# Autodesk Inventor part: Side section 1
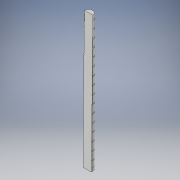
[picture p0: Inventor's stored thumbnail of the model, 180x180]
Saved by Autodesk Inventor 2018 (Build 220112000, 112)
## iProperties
Created: 2018-10
Part Number: Side section 1
Material: Generic
Document SubType Name: Modeling
Designer: johne
Density: 1 g/cm^3
Appearance: Default
Author: johne
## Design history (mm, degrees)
sketch "Sketch1"
  geometry: L1 (0, 0)-(25.4, 0); L2 (25.4, 0)-(25.4, -76.2); L3 (25.4, -76.2)-(0, -76.2); L4 (0, -76.2)-(0, 0)
  constraints: 8 end point, 2 parallel, 1 horizontal, 1 perpendicular
  dimensions: "d0" = 25.4 distance of L2.end L3.end; "d1" = 76.2 distance of L1.end L2.end
extrude "Extrusion1" new body sketch "Sketch1" distance "d2" = 25.4; taper "d3" = 0 deg
sketch "Sketch3"
  geometry: L1 (-2.627, -64.34)-(-23.226, -64.34); L2 (-23.226, -64.34)-(-23.226, -10.419); L3 (-23.226, -10.419)-(-2.627, -10.419); L4 (-2.627, -10.419)-(-2.627, -64.34); 1 further point
  constraints: 8 end point, 2 parallel, 1 horizontal, 1 perpendicular
extrude "Extrusion2" join sketch "Sketch3" distance "d4" = 25.4; taper "d5" = 0 deg
sketch "Sketch4"
  geometry: L1 (9.188, -40.142)-(9.188, 0); L2 (65.781, 0)-(-10.419, 0) reference; L3 (49.65, -33.733)-(49.65, 0); L4 (49.65, -33.733)-(75.988, -33.733); L5 (75.988, -33.733)-(75.988, 0); L6 (75.988, 0)-(49.65, 0); L7 (49.65, 0)-(49.65, -33.733); L8 (9.188, 0)-(-27.007, 0); L9 (-27.007, 0)-(-27.007, -40.142); L10 (-27.007, -40.142)-(9.188, -40.142); L11 (9.188, -40.142)-(9.188, 0); A1 r 0.762 centre (49.65, -33.733) between (49.77, -34.486) and (49.531, -32.981) reference; A2 r 0.762 centre (9.188, -40.142) between (9.846, -39.758) and (8.53, -40.527) reference; 1 further point
  constraints: 20 end point, 4 parallel, 3 perpendicular, 2 horizontal, 2 point on circle, 2 point on line, 1 centre point, 1 vertical, 4 other
extrude "Extrusion3" cut sketch "Sketch4" distance "d6" = 25.4; taper "d7" = 0 deg
sketch "Sketch5"
  geometry: L1 (17.911, -0.752)-(29.845, -0.752); L2 (29.845, -0.752)-(29.845, 25.4); L3 (29.845, 25.4)-(17.911, 25.4); L4 (17.911, 25.4)-(17.911, -0.752); L5 (2.925, -7.161)-(-11.223, -7.161); L6 (-11.223, -7.161)-(-11.223, 25.4); L7 (-11.223, 25.4)-(2.925, 25.4); L8 (2.925, 25.4)-(2.925, -7.161); 5 further points; 2 other entities
  constraints: 16 end point, 4 parallel, 2 horizontal, 2 perpendicular, 1 point on line, 2 other
extrude "Extrusion4" cut sketch "Sketch5" distance "d8" = 76.2; taper "d9" = 0 deg
sketch "Sketch6"
  geometry: L1 (-20.538, -19.607)-(-20.538, -60.069) reference; L2 (-20.538, -26.89)-(-20.538, -19.607); L3 (-20.538, -19.607)-(-13.045, -19.607); A1 r 7.62 centre (-12.926, -27.226) between (-13.045, -19.607) and (-20.538, -26.89); 1 further point
  constraints: 4 end point, 2 point on circle, 1 centre point, 1 collinear, 1 perpendicular, 2 other
  dimensions: "d10" = 7.62 radius of A1
extrude "Extrusion5" cut sketch "Sketch6" stored distance "d11" = 76.2; taper "d12" = 0 deg
workplane "Work Plane1"
workplane "Work Plane2"
mirror "Mirror1"
mirror "Mirror2"
sketch "Sketch7"
  geometry: L1 (-5.552, -52.785)-(-5.552, -26.89) reference; L2 (-20.538, -26.89)-(-20.538, -52.785) reference; A1 r 7.62 centre (-13.165, -52.45) between (-13.045, -60.069) and (-5.552, -52.785) reference; A2 r 7.62 centre (-13.165, -27.226) between (-5.552, -26.89) and (-13.045, -19.607) reference; A3 r 7.62 centre (-12.926, -27.226) between (-13.045, -19.607) and (-20.538, -26.89) reference; A4 r 7.62 centre (-12.926, -52.45) between (-20.538, -52.785) and (-13.045, -60.069) reference; 1 further point
extrude "Extrusion6" join sketch "Sketch7" distance "d13" = 184.15; taper "d14" = 0 deg
feature "Sculpt1"
sketch "Sketch8"
  geometry: C1 r 0.762 at (0, 0) reference; 1 further point
extrude "Extrusion7" cut sketch "Sketch8" distance "d15" = 184.15; taper "d16" = 0 deg
sketch "Sketch10"
  geometry: L1 (56.593, -27.851)-(56.593, -39.145) reference; L2 (49.31, -25.4)-(56.593, -25.4) reference; L3 (56.593, -25.4)-(62.943, -25.4); L4 (76.2, -25.4)-(0, -25.4) reference; L5 (23.415, -25.4)-(16.131, -25.4) reference; L6 (16.131, -25.4)-(9.781, -25.4); L7 (9.781, -25.4)-(-4.173, -25.4); L8 (-4.173, -25.4)-(-4.173, 6.216); L9 (-4.173, 6.216)-(9.781, 6.216); L10 (9.781, 6.216)-(9.781, -25.4); L11 (62.943, -25.4)-(76.826, -25.4); L12 (76.826, -25.4)-(76.826, 0); L13 (76.826, 0)-(62.943, 0); L14 (62.943, 0)-(62.943, -25.4); 3 further points; 1 other entity
  constraints: 20 end point, 4 parallel, 2 horizontal, 2 perpendicular, 2 point on line, 1 coincident
  dimensions: "d19" = 6.35 distance of L2.end L3.end; "d20" = 6.35 distance of L5.end L6.end
extrude "Extrusion9" cut sketch "Sketch10" distance "d21" = 50.8; taper "d22" = 0 deg
sketch "Sketch11"
  geometry: L1 (0, -25.4)-(53.163, -25.4) reference; L2 (53.163, -25.4)-(53.163, -12.7); L3 (53.163, 0)-(53.163, -25.4) reference; L4 (-7.051, -12.7)-(-7.051, 2.628); L5 (-7.051, 2.628)-(53.163, 2.628); L6 (53.163, 2.628)-(53.163, -12.7); L7 (-7.051, -12.7)-(-7.051, -25.4); L8 (-7.051, -25.4)-(53.163, -25.4); 1 further point
  constraints: 12 end point, 1 midpoint, 1 parallel, 1 perpendicular, 1 vertical
extrude "Extrusion10" cut sketch "Sketch11" distance "d23" = 50.8; taper "d24" = 0 deg
sketch "Sketch14"
  geometry: L1 (-14.986, 25.895)-(-14.986, 0) reference; L2 (0, 0)-(0, 25.895) reference; L3 (-0.375, 25.887)-(-0.375, 0.008); L4 (-14.612, 0.008)-(-14.612, 25.887); A1 r 7.62 centre (-7.613, 25.56) between (0, 25.895) and (-7.493, 33.179) reference; A2 r 7.62 centre (-7.374, 25.56) between (-7.493, 33.179) and (-14.986, 25.895) reference; A3 r 7.62 centre (-7.613, 0.335) between (-7.493, -7.284) and (0, 0) reference; A4 r 7.62 centre (-7.374, 0.335) between (-14.986, 0) and (-7.493, -7.284) reference; A5 r 7.245 centre (-7.613, 25.56) between (-0.375, 25.887) and (-7.493, 32.804); A6 r 7.245 centre (-7.613, 0.335) between (-7.493, -6.909) and (-0.375, 0.008); A7 r 7.245 centre (-7.374, 0.335) between (-14.612, 0.008) and (-7.493, -6.909); A8 r 7.245 centre (-7.374, 25.56) between (-7.493, 32.804) and (-14.612, 25.887); 1 further point
  constraints: 8 point on circle, 4 centre point, 4 end point, 5 other
  dimensions: "d36" = 0.37465 radial gap between concentric circles of A1 A5
extrude "Extrusion13" cut sketch "Sketch14" distance "d37" = 300; taper "d38" = 0 deg
sketch "Sketch15"
  geometry: L1 (-20.164, -26.899)-(-20.164, -52.777) reference; L2 (-5.927, -52.777)-(-5.927, -26.899) reference; L3 (-19.976, -52.773)-(-19.976, -26.903); L4 (-6.114, -26.903)-(-6.114, -52.773); A1 r 7.245 centre (-12.926, -27.226) between (-13.045, -19.981) and (-20.164, -26.899) reference; A2 r 7.245 centre (-12.926, -52.45) between (-20.164, -52.777) and (-13.045, -59.694) reference; A3 r 7.245 centre (-13.165, -52.45) between (-13.045, -59.694) and (-5.927, -52.777) reference; A4 r 7.245 centre (-13.165, -27.226) between (-5.927, -26.899) and (-13.045, -19.981) reference; A5 r 7.058 centre (-12.926, -27.226) between (-13.045, -20.169) and (-19.976, -26.903); A6 r 7.058 centre (-13.165, -27.226) between (-6.114, -26.903) and (-13.045, -20.169); A7 r 7.058 centre (-13.165, -52.45) between (-13.045, -59.507) and (-6.114, -52.773); A8 r 7.058 centre (-12.926, -52.45) between (-19.976, -52.773) and (-13.045, -59.507); 1 further point
  constraints: 8 point on circle, 4 centre point, 4 end point, 5 other
  dimensions: "d39" = 0.18733 distance between parallel lines of L1 L3
loft "Loft1" sketch "Sketch15" dims "d40" = 0, "d41" = 90 deg, "d42" = 0, "d43" = 90 deg
  node "Edges1"
node "Direct Edit2"
sketch "Sketch18"
  geometry: L1 (0, 0)-(0, 24.576) reference; L2 (13.169, 24.576)-(13.169, 0) reference; 3 further points
  constraints: 4 other
extrude "Extrusion16" join sketch "Sketch18" distance "d52" = 5; taper "d53" = 0 deg
workplane "Work Plane3"
workplane "Work Plane4"
workplane "Work Plane5"
workplane "Work Plane6"
workplane "Work Plane7"
sketch "Sketch23"
  geometry: L1 (-26.638, 23.659)-(17.833, 23.659); L2 (17.833, 23.659)-(17.833, -223.257); L3 (17.833, -223.257)-(-26.638, -223.257); L4 (-26.638, -223.257)-(-26.638, 23.659); 1 further point
  constraints: 8 end point, 2 parallel, 1 horizontal, 1 perpendicular
extrude "Extrusion19" cut sketch "Sketch23" distance "d67" = 100; taper "d68" = 0 deg
body "Solid1"
node "Reference1"
node "Reference2"
node "Reference3"
node "Projected Loop1"
node "Projected Loop2"
node "Projected Loop3"
feature "Composite1"
body "Srf1"
feature "Scale2"
other parameters: "d45" = 9.5, "d46" = 9.5
